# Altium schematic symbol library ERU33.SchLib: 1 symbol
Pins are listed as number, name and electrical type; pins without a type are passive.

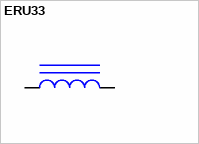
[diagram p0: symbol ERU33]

## ERU33
designator L?
Manufacturer: Used in BOM report; PartNumber: ERU33; SymbolVersion: use current date i.e. 2008-05-20; SymbolCreator: Use a-id; CompType: Used in some BOM reports.  Useful for finding later.; U/M: EA, IN, or GM
footprint ERU33
pins: 1, 2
